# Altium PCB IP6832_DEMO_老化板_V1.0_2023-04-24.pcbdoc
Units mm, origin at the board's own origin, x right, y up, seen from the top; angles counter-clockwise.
Board outline 78.7 x 89.5 mm, 2 copper layers (Top Layer, Bottom Layer); 45 components, 34 nets, 150 pads, 334 vias.
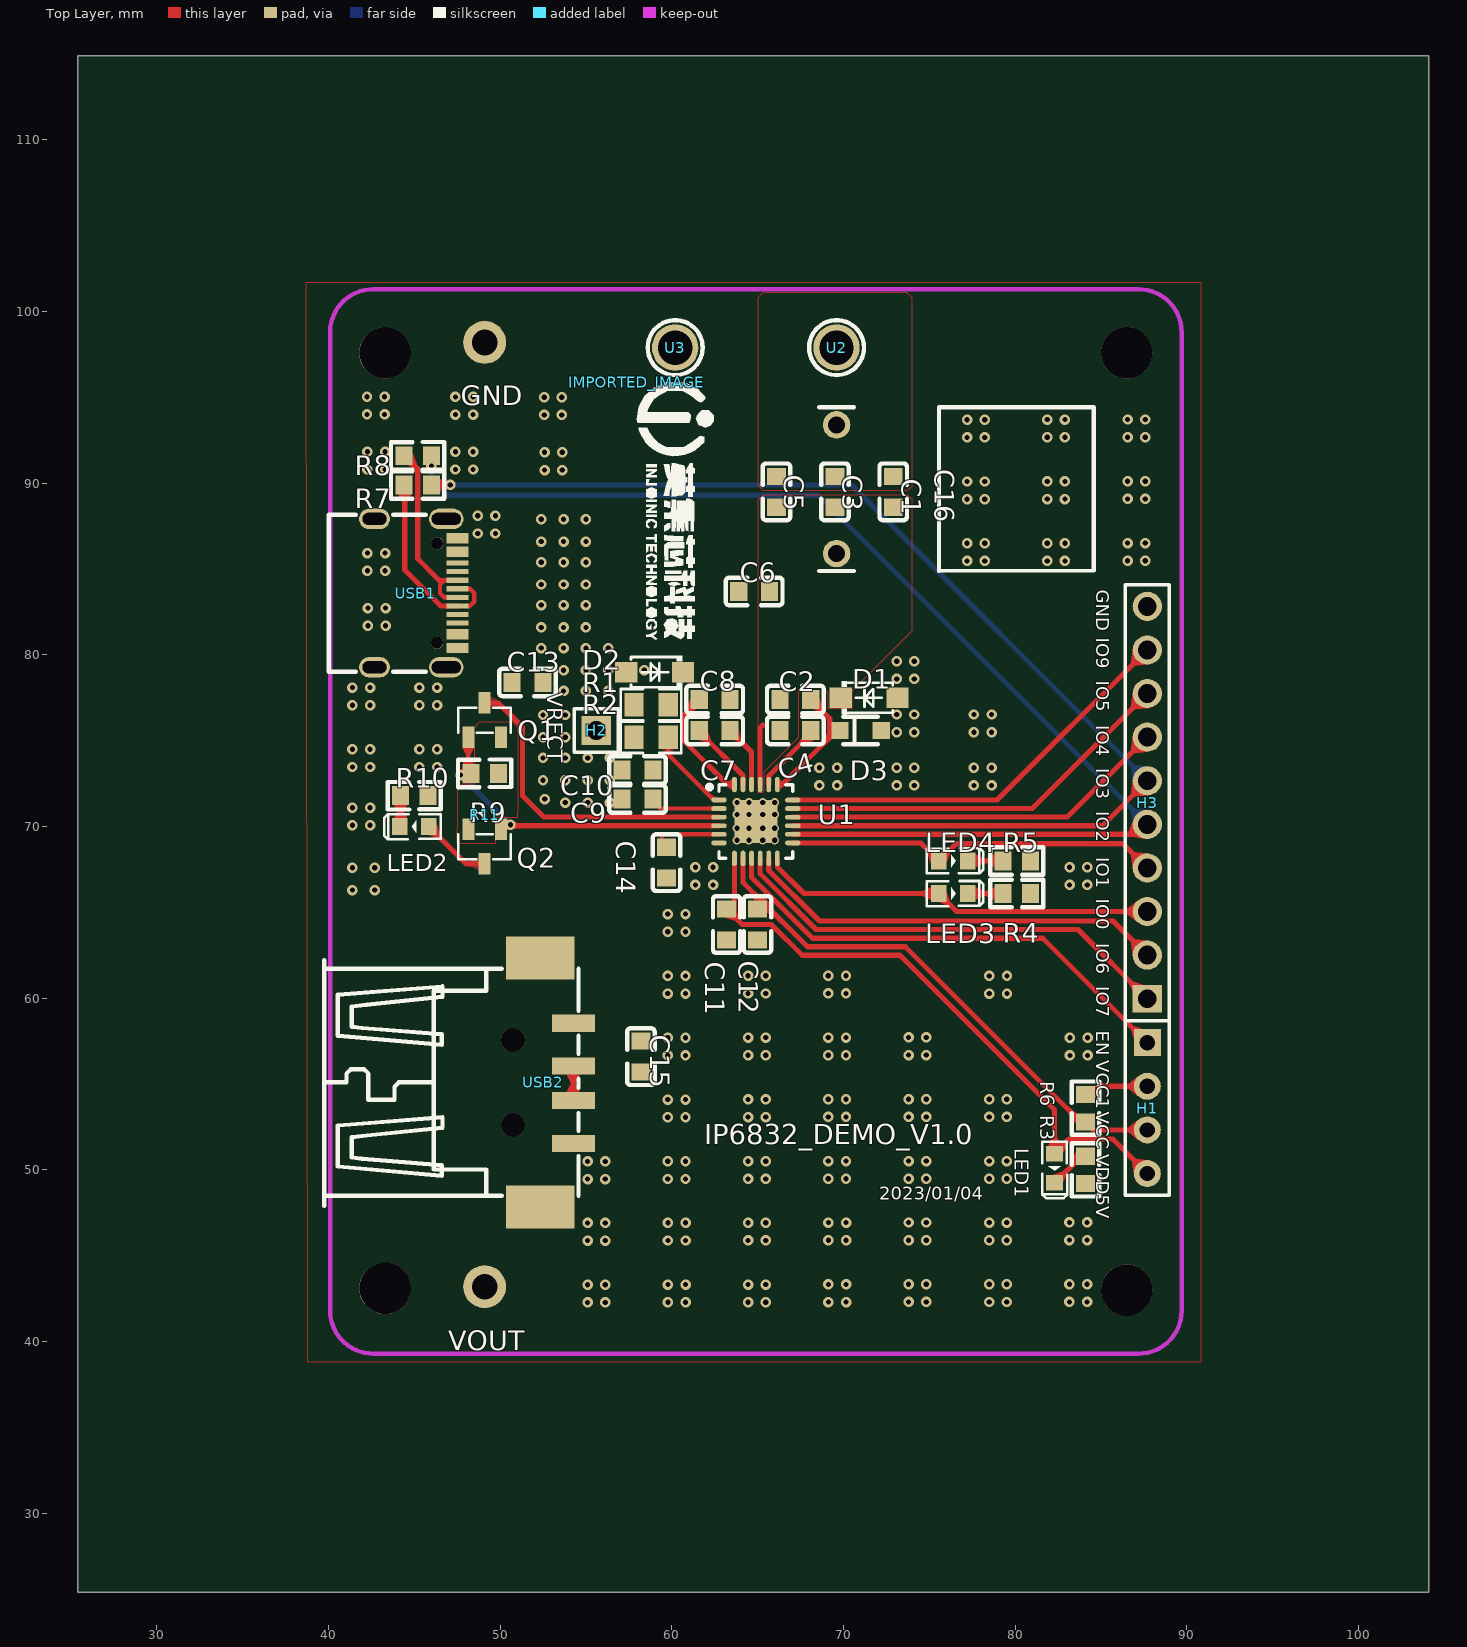
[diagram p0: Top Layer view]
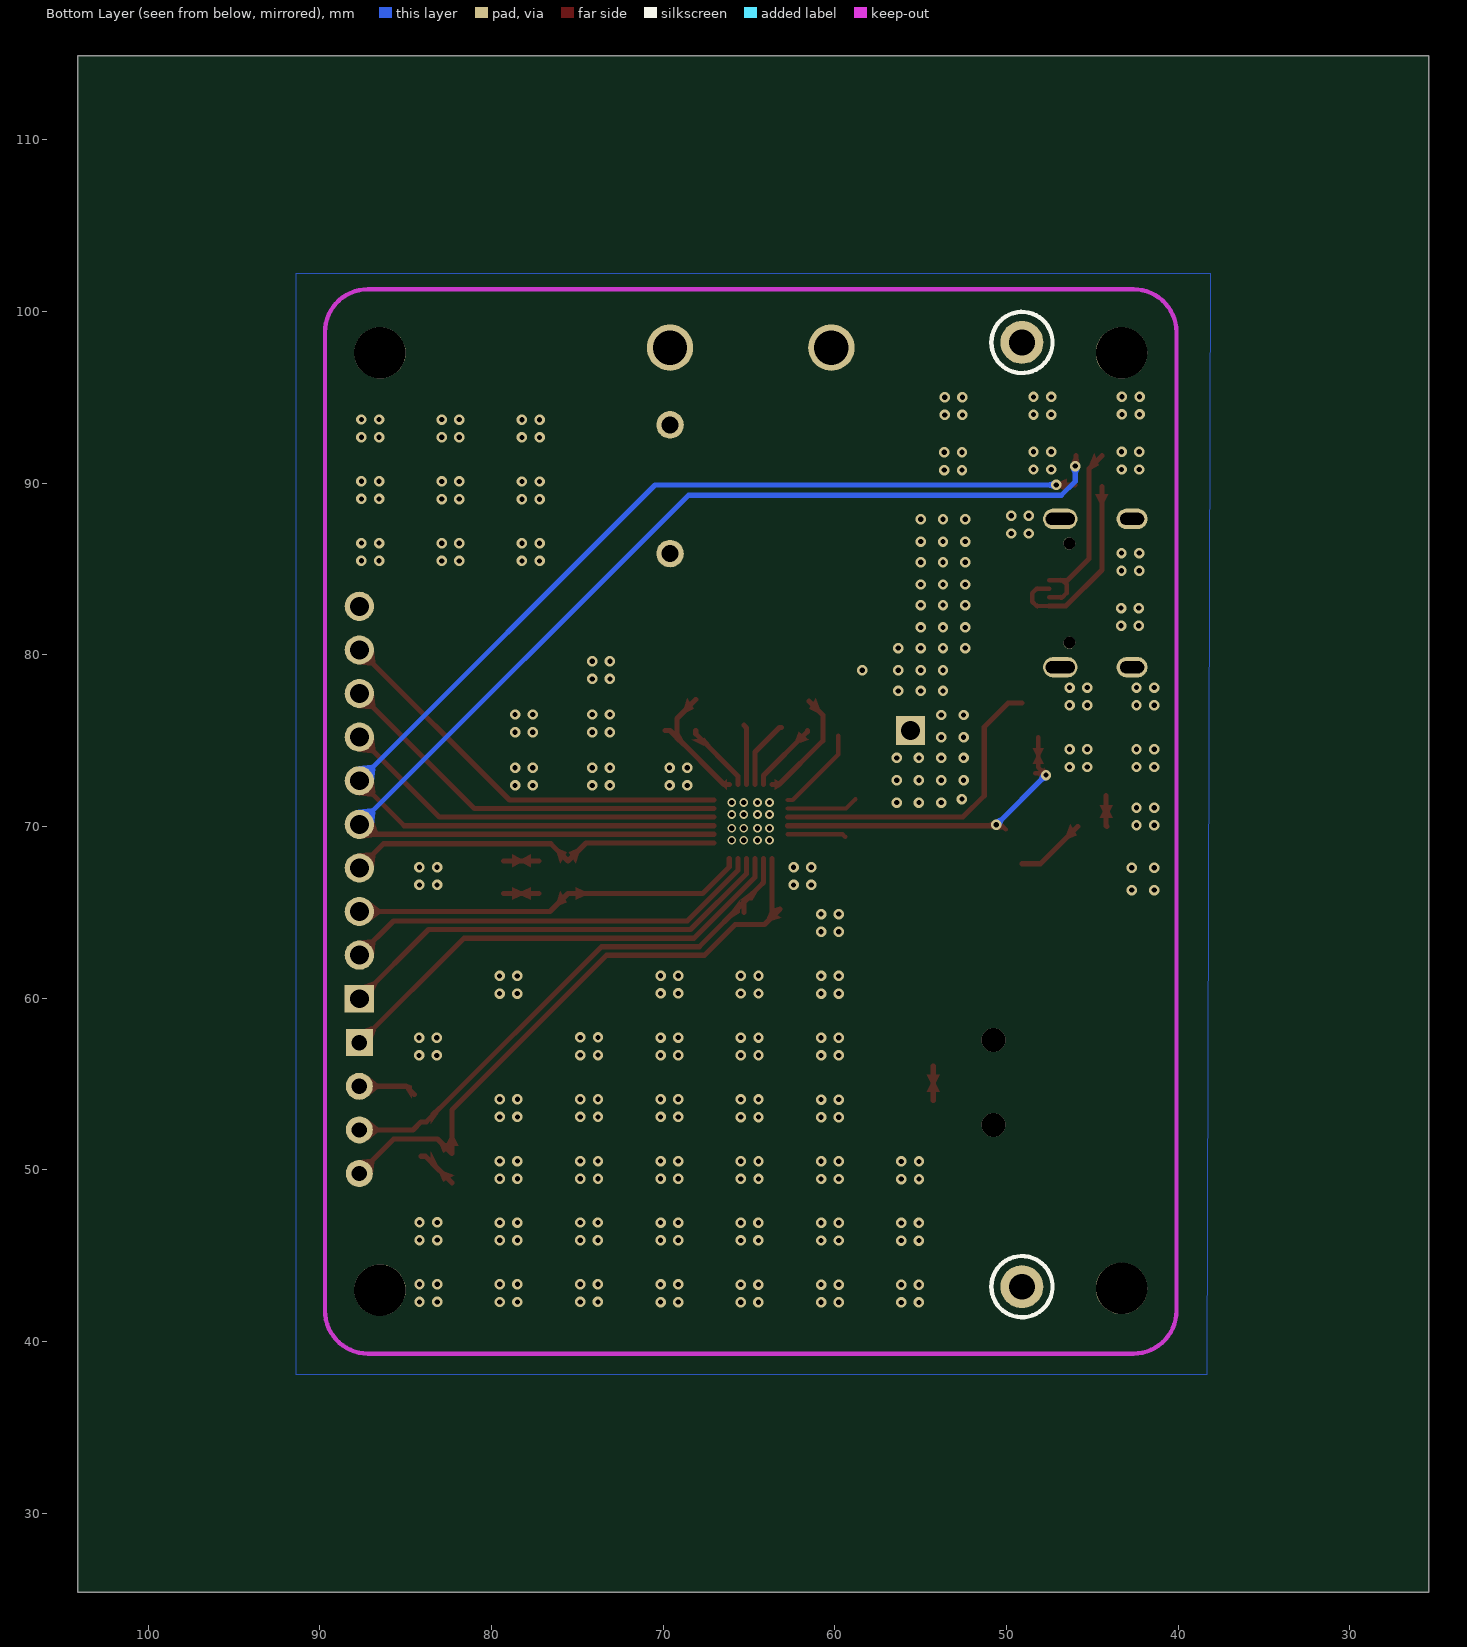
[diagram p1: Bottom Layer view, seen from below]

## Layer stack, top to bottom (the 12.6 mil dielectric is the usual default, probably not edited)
Top Layer: signal copper (thickness not stored)
Dielectric: dielectric 0.32, FR-4, Dk 4.8
Bottom Layer: signal copper (thickness not stored)

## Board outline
104.1,25.4 25.4,25.4 25.4,114.9 104.1,114.9

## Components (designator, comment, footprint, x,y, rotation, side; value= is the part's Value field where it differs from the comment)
C1 "NC" C0603 72.9,89.5 r90 top
C2 "22nf" C0603 67.2,77.4 r180 top
C3 "NC" C0603 69.5,89.5 r90 top
C4 "22nf" C0603 67.2,75.6 r180 top
C5 "NC" C0603 66.1,89.5 r90 top
C6 "2.2nF" C0603 64.8,83.7 r0 top
C7 "22nf" C0603 62.5,75.6 r180 top
C8 "22nf" C0603 62.5,77.4 r180 top
C9 "10uf" C0603 58,71.6 r0 top
C10 "10uf" C0603 58,73.3 r0 top
C11 "2.2uf" C0603 63.2,64.3 r90 top
C12 "2.2uf" C0603 65,64.3 r90 top
C13 "10uf" C0603 51.6,78.4 r180 top
C14 "10uf" C0603 59.7,67.9 r90 top
C15 "10uf" C0603 58.2,56.6 r90 top
C16 "250nF" CAP-TH_L15-W9-P7.50-D0.6 69.6,93.4 r270 top
D1 "NC" SOD-123FL_L2.8-W1.8-LS3.8-R-RD 71.5,77.5 r0 top
D2 "NC" SOD-123FL_L2.8-W1.8-LS3.8-R-RD 59,79 r180 top
D3 "B5819WS" SOD-323_L1.8-W1.3-LS2.5-RD 71,75.6 r0 top
H1 "HDR-M-2.54_1x4" HDR-M-2.54_1X4 87.7,53.6 r270 top
H2 "Header-Male-2.54_1x1" HDR-TH_1P-P2.54-V-M 55.6,75.6 r0 top
H3 "Header-Male-2.54_1x10" HDR-TH_10P-P2.54-V-M-1 87.7,71.4 r90 top
IMPORTED_IMAGE "IMPORTED_IMAGE" IMPORTED_IMAGE 57.951,95.871 r0 top
LED1 "LED" LED0603_RED 82.3,50.1 r270 top
LED2 "LED" LED0603_RED 45,70 r180 top
LED3 "LED" LED0603_RED 76.4,66.1 r0 top
LED4 "LED" LED0603_RED 76.4,68 r0 top
Q1 "CJ2301" SOT-23-3_L2.9-W1.3-P1.90-LS2.4-BR 49.1,76.2 r270 top
Q2 "CJ2301" SOT-23-3_L2.9-W1.3-P1.90-LS2.4-BR 49.1,68.832 r90 top
R1 "330R" R0805 58.8,77.1 r0 top
R2 "330R" R0805 58.8,75.2 r0 top
R3 "1k" R0603 84.1,50 r90 top
R4 "1k" R0603 80.1,66.1 r180 top
R5 "1k" R0603 80.1,68 r180 top
R6 "47k" R0603 84.1,53.6 r90 top
R7 "0R" R0603 45.2,89.9 r180 top
R8 "0R" R0603 45.2,91.6 r180 top
R9 "47k" R0603 49.1,73.1 r0 top
R10 "1k" R0603 45,71.8 r180 top
R11 "NC" R_P55 49.1,98.2 r270 top
U1 "IP6832" QFN-24_L4.0-W4.0-P0.50-BL-EP2.5 64.901,70.299 r0 top
U2 "TP" TESTPOINT-TH_BD3.2 69.6,97.9 r0 top
U3 "TP" TESTPOINT-TH_BD3.2 60.2,97.9 r0 top
USB1 "KH-TYPE-C-16P" USB-C-SMD_KH-TYPE-C-16P 45.101,83.6 r270 top
USB2 "USB-302S" USB-A-SMD_USB-302S 53.301,55.1 r270 top

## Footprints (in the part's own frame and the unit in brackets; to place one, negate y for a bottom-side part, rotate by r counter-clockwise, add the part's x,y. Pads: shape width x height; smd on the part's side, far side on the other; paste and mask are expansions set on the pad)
C0603 [mm]
  rect 1x1.1 smd: 1(-0.9,0) 2(0.9,0)
  silkscreen extent -1.65,-0.8 1.65,0.8
CAP-TH_L15-W9-P7.50-D0.6 [mm]
  round 1.6 hole 1: 1(0,0) 2(7.5,0)
  silkscreen extent -1.02,-1.01 8.51,14.99
HDR-M-2.54_1X4 [mil]
  rect 62x62 hole 35: 1(-150,0)
  round 62 hole 35: 2(-50,0) 3(50,0) 4(150,0)
  silkscreen extent -200,-50 200,50
HDR-TH_1P-P2.54-V-M [mm]
  rect 1.7x1.7 hole 1.1: 1(0,0)
  silkscreen extent -1.27,-1.27 1.27,1.27
HDR-TH_10P-P2.54-V-M-1 [mm]
  rect 1.575x1.7 hole 1.1: 1(-11.43,0)
  round 1.7 hole 1.1: 2(-8.89,0) 3(-6.35,0) 4(-3.81,0) 5(-1.27,0) 6(1.27,0) 7(3.81,0) 8(6.35,0) 9(8.89,0) 10(11.43,0)
  silkscreen extent -12.7,-1.27 12.7,1.27
IMPORTED_IMAGE [mm]
  silkscreen extent 0,-15 4.5,0
LED0603_RED [mm]
  rect 0.9x1 smd: 1(-0.85,0) 2(0.85,0)
  silkscreen extent -1.54,-0.73 1.75,0.73
QFN-24_L4.0-W4.0-P0.50-BL-EP2.5 [mm]
  oval 0.9x0.28 smd: 1(-2.15,1.25) 2(-2.15,0.75) 3(-2.15,0.25) 4(-2.15,-0.25) 5(-2.15,-0.75) 6(-2.15,-1.25) 13(2.15,-1.25) 14(2.15,-0.75) 15(2.15,-0.25) 16(2.15,0.25) 17(2.15,0.75) 18(2.15,1.242)
  oval 0.28x0.9 smd: 7(-1.25,-2.15) 8(-0.75,-2.15) 9(-0.25,-2.15) 10(0.25,-2.15) 11(0.75,-2.15) 12(1.25,-2.15) 19(1.25,2.15) 20(0.75,2.15) 21(0.25,2.15) 22(-0.25,2.15) 23(-0.75,2.15) 24(-1.25,2.15)
  rect 2.5x2.5 smd: 25(0,0)
  silkscreen extent -2.95,-2.15 2.15,2.25
R0603 [mm]
  rect 1x1.1 smd: 1(-0.8,0) 2(0.8,0)
  silkscreen extent -1.55,-0.8 1.55,0.81
R0805 [mm]
  rect 1.133x1.377 smd: 1(-1,0) 2(1,0)
  silkscreen extent -1.76,-0.92 1.76,0.92
R_P55 [mm]
  round 2.5 hole 1.5: 1(0,0) 2(55,0)
SOD-123FL_L2.8-W1.8-LS3.8-R-RD [mm]
  rect 1.3x1.2 smd: 1(1.65,0) 2(-1.65,0)
  silkscreen extent -1.6,-0.95 1.38,0.95
SOD-323_L1.8-W1.3-LS2.5-RD [mm]
  rect 1x1 smd: 1(-1.2,0) 2(1.2,0)
  silkscreen extent -1,-0.8 1,0.8
SOT-23-3_L2.9-W1.3-P1.90-LS2.4-BR [mm]
  rect 1.25x0.7 smd: 1(1,-0.95) 2(1,0.95) 3(-1,0)
  silkscreen extent -0.73,-1.53 0.73,1.53
TESTPOINT-TH_BD3.2 [mm]
  round 2.7 hole 2: 1(0,0)
  silkscreen extent -1.6,-1.6 1.6,1.6
USB-A-SMD_USB-302S [mm]
  rect 1x2.5 smd: 1(-3.445,0.965) 2(-0.944,0.965) 3(1.056,0.965) 4(3.555,0.965)
  rect 2.5x4 smd: 5(7.25,-0.965) 6(-7.25,-0.965)
  round 1.4 hole 1.4 unplated: ""(-2.47,-2.543) ""(2.478,-2.543)
  silkscreen extent -7.11,-13.54 7.2,1.27
USB-C-SMD_KH-TYPE-C-16P [mm]
  oval 1.2x2 hole 0.7 slot 1.7 at 90 deg: 1(-4.32,1.765) 2(4.32,1.765)
  oval 1.2x1.8 hole 0.7 slot 1.4 at 90 deg: 3(-4.32,-2.415) 4(4.32,-2.415)
  rect 0.3x1.3 smd: A1(-3.35,2.415) A4(-2.55,2.415) A5(-1.25,2.415) A6(-0.25,2.415) A7(0.25,2.415) A8(1.25,2.415) A9(2.55,2.415) A12(3.35,2.415) B1(3.05,2.415) B4(2.25,2.415) B5(1.75,2.415) B6(0.75,2.415) B7(-0.75,2.415) B8(-1.75,2.415) B9(-2.25,2.415) B12(-3.05,2.415)
  round 0.7 hole 0.7 unplated: ""(-2.89,1.235) ""(2.89,1.235)
  silkscreen extent -4.57,-5.08 4.57,0.57

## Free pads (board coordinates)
  round 3 hole 3 unplated: ""(43.3,43.1) ""(43.3,97.6) ""(86.5,43) ""(86.5,97.6)

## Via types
v1: diameter 0.61, hole 0.305, Top Layer to Bottom Layer, tented both sides, 318 vias
v2: diameter 0.508, hole 0.305, Top Layer to Bottom Layer, tented both sides, 16 vias

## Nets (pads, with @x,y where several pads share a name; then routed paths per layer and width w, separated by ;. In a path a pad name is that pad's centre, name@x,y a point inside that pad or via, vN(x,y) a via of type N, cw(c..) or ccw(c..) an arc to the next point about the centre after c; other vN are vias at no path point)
C16_1: C1.2 C3.2 C5.2 C16.1 U2.1
DM: R8.2 USB1.A7 USB1.B7 | length 12
  Top Layer w0.254: 46.399,84.401 46.402,84.398 46.45,84.35 47.514,84.35 46.75,84.35 46.501,84.101 46.501,83.601 46.75,83.349 USB1.A7@47.514,83.349
  Top Layer w0.3: R8.2@44.446,91.599 45.2,90.847 45.2,85.6 46.45,84.35
DP: R7.2 USB1.A6 USB1.B6 | length 11.5
  Top Layer w0.254: USB1.B6@47.514,82.849 48.251,82.849 48.5,83.1 48.5,83.601 48.251,83.85 USB1.A6@47.514,83.85
  Top Layer w0.3: R7.2@44.446,89.801 44.446,84.952 46.549,82.849 USB1.B6@47.514,82.849
EN: H1.1 U1.9 | length 28.1
  Top Layer w0.3: U1.9@64.649,68.15 64.649,67.05 68.2,63.499 81.609,63.499 H1.1@87.7,57.411
GND: C9.1 C10.1 C11.1 C12.1 C13.1 C14.1 C15.1 D1.1 D2.1 D3.2 H3.10 R3.1 R4.1 R5.1 R10.1 R11.1 U1.6 U1.25 USB1.1 USB1.2 USB1.3 USB1.4 USB1.A1 USB1.A12 USB1.B1 USB1.B12 USB2.4 USB2.5 USB2.6
  other v1: 55.1,42.283 56.127,42.283 59.774,42.289 60.802,42.289 64.449,42.295 65.476,42.295 69.124,42.302 70.151,42.302 73.798,42.308 74.826,42.308 78.492,42.306 79.519,42.306 83.166,42.312 84.194,42.312 55.1,43.312 56.127,43.312 59.774,43.318 60.802,43.318 64.449,43.324 65.476,43.324 69.124,43.33 70.151,43.33 73.798,43.336 74.826,43.336 78.492,43.335 79.519,43.335 83.166,43.341 84.194,43.341 55.1,45.883 56.127,45.883 59.774,45.89 60.802,45.89 64.449,45.896 65.476,45.896 69.124,45.902 70.151,45.902 73.798,45.908 74.826,45.908 78.492,45.906 79.519,45.906 83.166,45.912 84.194,45.912 55.1,46.912 56.127,46.912 59.774,46.918 60.802,46.918 64.449,46.924 65.476,46.925 69.124,46.93 70.151,46.93 73.798,46.937 74.826,46.937 78.492,46.935 79.519,46.935 83.166,46.941 84.194,46.941 55.098,49.465 56.125,49.465 59.773,49.471 60.8,49.471 64.447,49.478 65.475,49.478 69.122,49.484 70.149,49.484 73.796,49.49 74.824,49.49 78.49,49.488 79.517,49.488 55.098,50.494 56.125,50.494 59.773,50.5 60.8,50.5 64.447,50.506 65.475,50.506 69.122,50.512 70.149,50.512 73.796,50.518 74.824,50.518 78.49,50.517 79.517,50.517 59.773,53.071 60.8,53.071 64.447,53.077 64.447,53.077 65.475,53.077 69.122,53.084 70.149,53.084 73.796,53.09 74.824,53.09 78.49,53.088 79.517,53.088 59.773,54.1 60.8,54.1 64.447,54.106 65.475,54.106 69.122,54.112 70.149,54.112 73.796,54.118 74.824,54.118 78.49,54.117 79.517,54.117 59.773,56.671 60.8,56.671 64.447,56.677 65.475,56.677 83.193,56.67 84.221,56.67 69.122,56.684 70.149,56.684 73.796,56.69 74.824,56.69 59.773,57.7 60.8,57.7 64.447,57.706 65.475,57.706 69.122,57.712 70.149,57.712 73.796,57.718 74.824,57.719 83.193,57.698 84.221,57.698 59.773,60.271 60.8,60.271 64.447,60.277 65.475,60.277 69.122,60.283 70.149,60.283 78.5,60.271 79.527,60.271 59.773,61.3 60.8,61.3 78.5,61.3 79.527,61.3 64.447,61.306 65.475,61.306 69.122,61.312 70.149,61.312 59.773,63.871 60.8,63.871 59.773,64.9 60.8,64.9 41.4,66.3 42.7,66.3 61.377,66.602 62.404,66.602 83.173,66.6 84.2,66.6 41.4,67.6 42.7,67.6 61.377,67.631 62.404,67.631 83.173,67.629 84.2,67.629 41.4,70.071 42.427,70.071 41.4,71.1 42.427,71.1 53.8,71.4 55.1,71.4 56.4,71.4 52.6,71.6 68.6,72.4 69.627,72.4 73.1,72.4 74.127,72.4 77.6,72.4 78.627,72.4 52.5,72.7 53.8,72.7 55.1,72.7 56.4,72.7 68.6,73.429 69.627,73.429 73.1,73.429 74.127,73.429 77.6,73.429 78.627,73.429 41.4,73.471 42.427,73.471 45.3,73.471 46.327,73.471 52.5,74 53.8,74 55.1,74 56.4,74 41.4,74.5 42.427,74.5 45.3,74.5 46.327,74.5 52.5,75.2 53.8,75.2 73.1,75.5 74.127,75.5 77.6,75.5 78.627,75.5 52.5,76.5 53.8,76.5 73.1,76.529 74.127,76.529 77.6,76.529 78.627,76.529 41.4,77.071 42.427,77.071 45.3,77.071 46.327,77.071 53.7,77.9 55,77.9 56.3,77.9 41.4,78.1 42.427,78.1 45.3,78.1 46.327,78.1 73.1,78.601 74.127,78.601 53.7,79.1 55,79.1 56.3,79.1 58.4,79.1 73.1,79.629 74.127,79.629 52.4,80.4 53.7,80.4 55,80.4 56.3,80.4 52.4,81.6 53.7,81.6 55,81.6 42.3,81.7 43.327,81.7 42.3,82.729 43.327,82.729 52.4,82.9 53.7,82.9 55,82.9 52.4,84.1 53.7,84.1 55,84.1 42.274,84.906 43.302,84.906 52.4,85.4 53.7,85.4 55,85.4 77.2,85.471 78.227,85.471 81.875,85.477 82.902,85.477 86.549,85.483 87.577,85.483 42.274,85.935 43.302,85.935 77.2,86.5 78.227,86.5 81.875,86.506 82.902,86.506 86.549,86.512 87.577,86.512 52.4,86.6 53.7,86.6 55,86.6 48.7,87.071 49.727,87.071 52.4,87.9 53.7,87.9 55,87.9 48.7,88.1 49.727,88.1 77.2,89.071 78.227,89.071 81.875,89.077 82.902,89.077 86.549,89.083 87.577,89.083 77.2,90.1 78.227,90.1 81.875,90.106 82.902,90.106 86.549,90.112 87.577,90.112 52.594,90.77 53.621,90.77 42.272,90.8 43.3,90.8 47.4,90.8 48.427,90.8 52.594,91.798 53.621,91.798 42.272,91.828 43.3,91.829 47.4,91.828 48.427,91.828 77.2,92.671 78.227,92.671 81.875,92.677 82.902,92.677 86.549,92.683 87.577,92.683 77.2,93.7 78.227,93.7 81.875,93.706 82.902,93.706 86.549,93.712 87.577,93.712 52.568,93.976 53.596,93.976 42.247,94.006 43.274,94.006 47.4,94 48.427,94 52.568,95.004 53.596,95.004 47.4,95.029 48.427,95.029 42.247,95.035 43.274,95.035
  other v2: 63.8,69.2 64.5,69.2 65.3,69.2 66,69.2 63.8,69.9 64.5,69.9 65.3,69.9 66,69.9 63.8,70.7 64.5,70.7 65.3,70.7 66,70.7 63.8,71.4 64.5,71.4 65.3,71.4 66,71.4
GPIO0: H3.3 LED3.1 U1.12 | length 23.1
  Top Layer w0.3: U1.12@66.15,68.15 66.15,67.649 67.7,66.1 LED3.1 76.6,65.051 H3.3@87.7,65.051
GPIO1: H3.4 LED4.1 U1.13 | length 22.1
  Top Layer w0.3: U1.13@67.049,69.049 74.502,69.049 LED4.1 76.552,69.001 86.29,69.001 H3.4@87.7,67.591
GPIO2: H3.5 R8.1 U1.14 | length 72.4
  Top Layer w0.3: R8.1@45.952,91.599 45.952,91.048 v1(46,91) ; U1.14@67.049,69.549 87.118,69.549 H3.5@87.7,70.131
  Bottom Layer w0.3: v1(46,91) 46,90.101 46.806,89.3 68.53,89.3 H3.5
GPIO3: H3.6 R7.1 U1.15 | length 70.6
  Top Layer w0.3: R7.1 v1(47.1,89.9) ; U1.15@67.049,70.052 85.083,70.052 H3.6@87.7,72.671
  Bottom Layer w0.3: v1(47.1,89.9) 70.471,89.9 H3.6
GPIO4: H3.7 U1.16 | length 22.6
  Top Layer w0.3: U1.16@67.049,70.55 83.039,70.55 H3.7@87.7,75.211
GPIO5: H3.8 U1.17 | length 23.4
  Top Layer w0.3: U1.17@67.049,71.051 80.999,71.051 H3.8@87.7,77.751
GPIO6: H3.2 U1.11 | length 24.8
  Top Layer w0.3: U1.11@65.65,68.147 65.65,67.449 68.599,64.5 85.711,64.5 H3.2@87.7,62.511
GPIO7: H3.1 U1.10 | length 26.5
  Top Layer w0.3: U1.10@65.149,68.15 65.149,67.251 68.401,63.999 83.671,63.999 H3.1@87.7,59.971
GPIO9: H3.9 U1.18 | length 24.3
  Top Layer w0.3: U1.18@67.049,71.543 78.952,71.543 H3.9@87.7,80.291
H1_2: H1.2 R6.2 | length 3.4
  Top Layer w0.3: R6.2@84.499,54.401 84.972,54.871 H1.2@87.7,54.871
LED2_2: LED2.2 R10.2 | length 1.8
  Top Layer w0.3: LED2.2 44.2,70.05 R10.2@44.2,71.8
PGATE: Q1.1 Q2.1 R9.1 U1.4 | length 20.7
  Top Layer w0.254: Q1.1@48.149,75.201 48.149,73.448 v1@47.7,73.001 ; Q2.1@50.049,69.831 50.318,70.101 v1@50.6,70.101 ; v1@47.7,73.001 R9.1@47.801,73.1 ; v1@47.7,73.001 R9.1@47.801,73.1 ; R9.1@47.801,73.1 48.325,73.1 R9.1@47.801,73.1
  Top Layer w0.3: v1@50.6,70.101 50.651,70.05 U1.4@62.749,70.05
  Bottom Layer w0.3: v1(47.7,73) v1(50.6,70.1)
Q1_2: Q1.2 Q2.2 R9.2
R3_2: LED1.2 R3.2 | length 2.4
  Top Layer w0.3: LED1.2@82.3,49.25 83.849,50.799 R3.2
R4_2: LED3.2 R4.2 | length 2
  Top Layer w0.3: LED3.2 R4.2
R5_2: LED4.2 R5.2 | length 2
  Top Layer w0.3: LED4.2 R5.2
U1_1: R1.2 R2.2 U1.1 | length 5.1
  Top Layer w0.254: R2.2@59.8,75.3 59.8,74.2 62.449,71.551 U1.1@62.749,71.551
U1_19: C2.1 D3.1 U1.19 | length 8.3
  Top Layer w0.3: U1.19@66.15,72.45 66.45,72.45 69.201,75.201 69.201,76.298 C2.1@68.101,77.401 ; 68.749,74.751 69.597,75.6 D3.1@69.899,75.6
U1_20: C4.1 U1.20 | length 4.2
  Top Layer w0.3: U1.20@65.65,72.45 65.65,72.95 68.101,75.402 C4.1
U1_21: C1.1 C2.2 C3.1 C4.2 C5.1 C6.2 C16.2 D1.2 U1.21 | length 3.5
  Top Layer w0.3: U1.21@65.149,72.45 65.149,75.75 65.299,75.899
U1_22: C6.1 C7.1 C8.1 D2.2 U1.22 U3.1 | length 4
  Top Layer w0.3: C7.1@63.1,75.767 63.232,75.767 63.399,75.6 64.649,74.35 U1.22@64.649,72.45
U1_23: C7.2 U1.23 | length 4.2
  Top Layer w0.3: C7.2 61.601,75.526 64.151,72.973 U1.23@64.151,72.45
U1_24: C8.2 U1.24 | length 6.6
  Top Layer w0.3: C8.2@61.499,77.299 60.699,76.504 60.699,75 63.25,72.45 U1.24@63.651,72.45
USB2_2: USB2.2 USB2.3 | length 2
  Top Layer w0.3: USB2.3@54.266,54.045 USB2.2
VBUS: C13.2 Q1.3 U1.3 USB1.A4 USB1.A9 USB1.B4 USB1.B9 | length 18.7
  Top Layer w0.3: Q1.3@49.099,77.2 49.899,77.2 51.299,75.8 51.299,71.8 52.549,70.55 U1.3@62.749,70.55
VCC: C12.2 H1.3 R6.1 U1.8 | length 31.9
  Top Layer w0.3: U1.8@64.151,68.15 64.151,66.748 64.2,66.699 65.299,65.6 C12.2@65.299,65 ; 65.055,65.844 67.9,62.999 73.6,62.999 83.801,52.801 84.1,52.801 84.57,52.331 H1.3@87.7,52.331
VDD5V: C11.2 H1.4 LED1.1 U1.7 | length 36.7
  Top Layer w0.3: U1.7@63.651,68.15 63.651,65.051 63.199,65.201 64.1,64.299 65.8,64.299 67.598,62.501 73.298,62.501 82.3,53.499 LED1.1@82.3,50.949 ; LED1.1@82.3,50.951 83.148,51.8 85.69,51.8 H1.4@87.7,49.791
VOUT: C14.2 C15.2 LED2.1 Q2.3 R11.2 U1.5 USB2.1 | length 7.6
  Top Layer w0.254: 59.401,69.4 59.551,69.549 U1.5@62.749,69.549
  Top Layer w0.3: LED2.1 48.02,67.832 Q2.3@49.099,67.832
VRECT: C9.2 C10.2 H2.1 R1.1 R2.1 U1.2 | length 4.2
  Top Layer w0.254: C9.2@58.799,71.599 59.348,71.051 U1.2@62.749,71.051
pads on no net: USB1. USB1.A5 USB1.A8 USB1.B5 USB1.B8 USB2.

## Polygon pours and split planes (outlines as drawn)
GND on Bottom Layer (solid): 38.1,102.2 91.4,102.2 91.4,38.1 38.3,38.1
U1_22 on Top Layer (solid): 64.8,72 64.7,72 64.5,72 64.4,72.1 64.4,73.2 63,74.6 62.8,74.8 62.4,75.2 62.3,75.3 62.3,78.1 62.1,78.3 60.1,78.3 55.8,82.6 55.8,100.8 56.1,101.1 64.6,101.1 64.8,100.8 64.7,83
U1_21 on Top Layer (solid): 65,72 65.1,72 65.3,72 65.4,72.1 65.4,73.2 66.8,74.6 67,74.8 67.1,74.9 67.4,75.2 67.4,75.8 67.4,78 67.6,78.2 68.7,78.2 69.1,77.8 69.1,76.9 70.5,76.9 70.5,77.9 70.8,78.2 71.4,78.8 74,81.4 74,89.1 73.7,89.3 65.3,89.3 65,89
C16_1 on Top Layer (solid): 66.2,101.1 65.3,101.1 65,100.8 65,89.9 65.3,89.6 73.2,89.6 73.7,89.6 74,89.8 74,100.8 73.7,101.1 67.3,101.1 66.9,101.1
VOUT on Top Layer (solid): 49.3,53.1 52.9,56.7 56.8,56.7 56.8,61 50.2,61 50.2,68.7 47.4,68.7 47.3,68.7 39.6,61 39.6,58.8 39.6,58.2 39.6,56.9 39.6,45.7 39.6,39.1 51.3,39.1 51.3,45 49.3,47 49.3,49.2 49.3,49.5 49.3,49.8
VOUT on Top Layer (solid): 63.2,69.7 63.1,69.8 62.3,69.8 58.5,69.8 57.7,69.8 57.1,69.8 54.2,69.8 51.1,69.8 50.3,68.8 47.68,68.75 47.3,68.7 47.1,68.1 47.28,68.15 47.28,66.65 47.3,56.7 58.6,56.7 58.9,57 58.8,66.9 58.8,67.7 59.1,68 60.8,68 62.2,69.3 63.1,69.3 63.2,69.4
Q1_2 on Top Layer (solid): 48.824,76.1 50.724,76.1 51.024,75.8 51.024,75.4 51.024,71.2 51,70.5 49.724,70.5 49.724,69 48.724,69 47.5,69 47.524,70.7 47.524,71.4 47.524,72.1 47.824,72.5 48.524,72.5 48.524,73.3 48.524,75.8
VBUS on Top Layer (solid): 51.6,82.2 51.6,81.6 51.6,80.8 51.6,80.1 51.6,78.9 51.6,78.5 51.6,78.1 49.7,76.3 47.5,76.3 47.5,77 47.5,77.3 47.5,77.6 47.5,78.3 47.5,78.6 48,79.2 48,79.8 48.2,80 48.2,80.7 46.7,80.7 46.7,83.6 46.7,85.5 46.7,86.3 50.7,86.3 51.6,85.4
GND on Top Layer (solid): 38.7,101.7 90.8,101.7 90.8,38.8 38.8,38.8
U1_1 on Top Layer (solid): 59.2,77.8 60.4,77.8 60.4,74.9 63.2,72 63.2,71.4 62.4,71.4 59.2,74.5
VRECT on Top Layer (solid): 55.2,76.6 56.5,76.6 57.2,77.2 57.2,77.8 58.7,77.8 58.7,74.8 59,74.5 62.3,71.2 63.2,71.2 63.2,70.9 58,70.9 58,73.9 56.5,74.7 55.2,74.7

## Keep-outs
Keep-Out Layer:
  lines w0.254: 40.1,41.8 ccw(c42.6,41.8) 42.6,39.3 ; 40.1,98.8 cw(c42.6,98.8) 42.6,101.3 ; 87.2,39.3 ccw(c87.2,41.8) 89.7,41.8 ; 87.2,101.3 cw(c87.2,98.8) 89.7,98.8

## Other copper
Top Layer:
  region net GPIO9: 86.851,80.343 87.753,79.442 86.988,79.366 86.775,79.578
  region net GPIO5: 86.851,77.803 87.753,76.902 86.988,76.826 86.775,77.038
  region net GPIO4: 86.851,75.263 87.753,74.362 86.988,74.286 86.775,74.498
  region net GPIO3: 86.851,72.723 87.753,71.822 86.988,71.746 86.775,71.958
  region net GPIO2: 87.533,69.296 86.894,70.399 86.612,69.699 86.786,69.399
  region net GPIO1: 86.851,67.537 87.753,68.438 86.988,68.514 86.775,68.302
  region net GPIO0: 87.138,64.413 87.138,65.688 86.543,65.2 86.543,64.9
  region net GPIO6: 86.851,62.457 87.753,63.358 86.988,63.434 86.775,63.222
  region net H1_2: 87.179,55.461 87.179,54.28 86.628,54.72 86.628,55.02
  region net VCC: 87.179,52.921 87.179,51.74 86.628,52.181 86.628,52.481
  region net VDD5V: 86.914,49.741 87.749,50.576 87.048,50.654 86.836,50.442
  region net PGATE: 50.828,70.303 50.773,69.849 50.994,69.9 51.03,70.2
  region net PGATE: 50.471,69.824 50.343,70.263 50.161,70.123 50.242,69.845
  region net PGATE: 47.951,72.827 47.84,73.271 48.071,73.227 48.134,72.973
  region net PGATE: 47.951,72.827 47.84,73.271 48.071,73.227 48.134,72.973
  region net PGATE: 48.004,72.981 47.681,73.304 47.904,73.383 48.083,73.203
  region net GPIO2: 46.204,91.226 45.75,91.174 45.802,91.395 46.102,91.429
  region net GPIO3: 46.898,89.671 46.898,90.128 46.685,90.05 46.685,89.75
  region net U1_19: 68.6,77.488 68.206,76.85 68.621,76.667 68.783,76.929
  region net U1_20: 68.339,75.05 67.6,75.178 67.267,74.78 67.628,74.717
  region net U1_23: 62.1,75.514 61.511,75.05 62.028,74.885 62.265,75.072
  region net U1_24: 61.492,76.85 61.1,77.489 60.915,76.929 61.076,76.666
  region net VDD5V: 63.75,65.094 63.111,64.7 63.671,64.516 63.934,64.678
  region net VCC: 65.55,65.7 65.55,64.974 66,64.687 66,65.111
  region net VCC: 64.824,65.7 65.55,65.7 65.268,65.844 64.949,65.737
  region net VCC: 64.825,65.7 65.55,65.7 64.962,66.15 64.538,66.15
  region net U1_19: 69.318,75.1 69.3,75.85 68.868,75.083 68.878,74.668
  region net R3_2: 83.572,50.3 83.55,51.05 83.122,50.285 83.134,49.872
  region net R4_2: 78.8,65.725 78.8,66.475 78.35,66.25 78.35,65.95
  region net R5_2: 78.8,67.625 78.8,68.375 78.35,68.15 78.35,67.85
  region net H1_2: 84.65,54.9 84.65,54.175 84.971,54.659 84.865,54.977
  region net VCC: 83.55,52.675 83.55,53.3 83.1,53.712 83.1,53.288
  region net DP: 44.821,89.35 44.071,89.35 44.296,88.9 44.596,88.9
  region net GPIO3: 46.5,90.275 46.5,89.525 46.95,89.75 46.95,90.05
  region net DM: 44.9,91.752 44.637,91.05 45.027,90.808 45.143,91.117
  region net GPIO2: 46.327,91.05 45.577,91.05 45.802,91.048 46.102,91.048
  region net PGATE: 47.8,72.782 47.8,73.417 47.7,73.179 47.788,72.91
  region net PGATE: 47.8,72.782 47.8,73.417 47.7,73.179 47.788,72.91
  region net PGATE: 47.8,72.784 47.8,73.419 47.7,73.18 47.789,72.911
  region net PGATE: 47.832,73.65 48.467,73.65 48.276,74.031 48.022,74.031
  region net LED2_2: 44.575,71.25 43.825,71.25 44.05,70.8 44.35,70.8
  region net DM: 46.866,84.2 46.866,84.5 46.75,84.477 46.75,84.223
  region net DM: 46.866,84.2 46.866,84.5 46.485,84.477 46.485,84.223
  region net DP: 48.166,84 48.166,83.7 48.251,83.723 48.251,83.977
  region net DM: 46.866,83.2 46.866,83.5 46.75,83.476 46.75,83.222
  region net DP: 48.166,83 48.166,82.7 48.251,82.722 48.251,82.976
  region net USB2_2: 53.891,54.544 54.641,54.544 54.416,54.994 54.116,54.994
  region net USB2_2: 54.641,55.545 53.891,55.545 54.116,55.095 54.416,55.095
  region net GPIO7: 86.85,60.399 87.509,60.757 86.928,60.954 86.653,60.804
  region net EN: 86.912,57.667 87.443,58.197 86.965,58.357 86.753,58.144
  region net R4_2: 77.7,66.475 77.7,65.725 78.15,65.95 78.15,66.25
  region net GPIO0: 76,66.24 75.608,65.6 76.023,65.416 76.184,65.679
  region net GPIO0: 75.1,65.725 75.1,66.475 74.65,66.25 74.65,65.95
  region net R5_2: 77.7,68.375 77.7,67.625 78.15,67.85 78.15,68.15
  region net GPIO1: 75.608,68.5 76,67.861 76.184,68.421 76.023,68.684
  region net GPIO1: 75.1,67.864 75.497,68.5 75.08,68.682 74.917,68.421
  region net PGATE: 48.467,74.575 47.832,74.575 48.022,74.194 48.276,74.194
  region net PGATE: 50.4,70.418 50.4,69.783 50.6,69.974 50.6,70.228
  region net R3_2: 82.161,49.7 82.8,49.307 82.984,49.722 82.721,49.884
  region net VDD5V: 81.925,51.399 82.675,51.399 82.45,51.849 82.15,51.849
  region net VDD5V: 82.158,51.399 82.8,51.012 82.986,51.426 82.721,51.585
  region net LED2_2: 43.825,70.5 44.575,70.5 44.35,70.95 44.05,70.95
  region net VOUT: 46.3,70.138 45.905,69.5 46.321,69.317 46.483,69.579
  region net U1_24: 63.511,72.139 63.511,72.759 63.25,72.6 63.25,72.3
  region net U1_19: 66.291,72.759 66.291,72.139 66.45,72.3 66.45,72.6
Bottom Layer:
  region net GPIO3: 86.851,72.617 87.753,73.518 86.988,73.594 86.775,73.382
  region net GPIO2: 86.851,70.077 87.753,70.978 86.988,71.054 86.775,70.842
  region net PGATE: 50.619,70.404 50.296,70.081 50.201,70.287 50.413,70.499
  region net PGATE: 48.004,73.019 47.681,72.696 47.887,72.6 48.099,72.813
  region net GPIO2: 46.229,90.798 45.771,90.798 45.85,90.585 46.15,90.585
  region net GPIO3: 47.302,89.671 47.302,90.128 47.515,90.05 47.515,89.75

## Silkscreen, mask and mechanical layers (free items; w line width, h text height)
Top Overlay:
  text "GND" at 47.7,94.528 h1.14
  text "GND" at 84.719,83.8 h0.76 r270
  text "IO9" at 84.719,81 h0.76 r270
  text "IO5" at 84.719,78.5 h0.76 r270
  text "VRECT" at 52.75,77.8 h0.9 r270
  text "IO4" at 84.719,75.9 h0.76 r270
  text "IO3" at 84.719,73.4 h0.76 r270
  text "IO2" at 84.719,70.9 h0.76 r270
  text "IO1" at 84.719,68.2 h0.76 r270
  text "IO0" at 84.719,65.8 h0.76 r270
  text "IO6" at 84.719,63.2 h0.76 r270
  text "IO7" at 84.719,60.7 h0.76 r270
  text "EN" at 84.719,58.1 h0.76 r270
  text "VCC1" at 84.719,56.4 h0.76 r270
  text "VCC" at 84.719,53.4 h0.76 r270
  text "IP6832_DEMO_V1.0" at 61.9,51.1 h2
  text "VDD5V" at 84.719,50.9 h0.76 r270
  text "2023/01/04" at 72.1,48 h1.3
  text "VOUT" at 46.973,39.5 h1.14
Bottom Solder:
  region: 57.8,78.8 72,78.8 72,78.5 72,61.8 57.8,61.8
